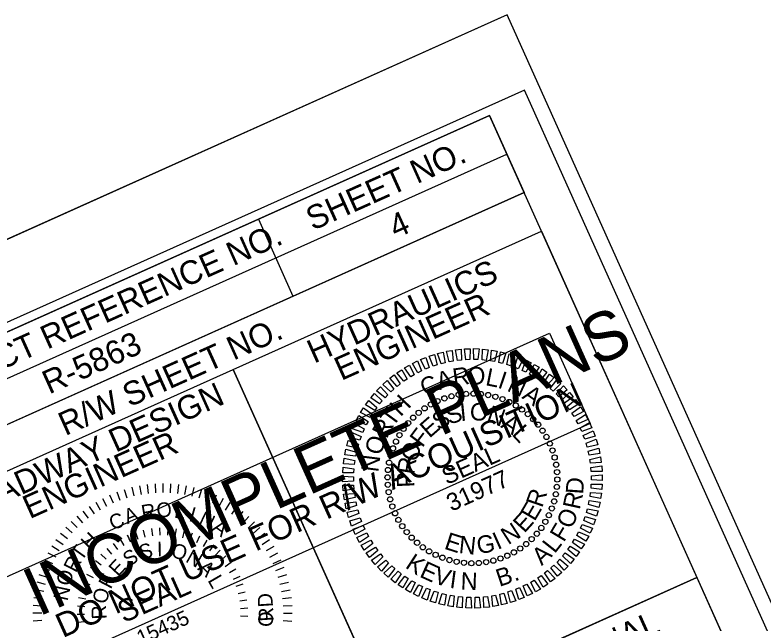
# Model space of a CAD drawing. Extents: x 553939 to 555925, y 502653 to 504347.
# Drawn here: x 555329.1 to 555550.6, y 504166.5 to 504346.6 of the extents above; entities that cross this region are included whole.
import ezdxf

# ---------------------------------------------------------------- set-up
doc = ezdxf.new("R2010")
doc.units = 0
for name, color, linetype in [('Default', 7, 'Continuous'), ('Old_Level_21', 7, 'Continuous'), ('Sheet Border Standard 30in CELL', 7, 'Continuous'), ('Sheet Cutting Line CELL', 7, 'Continuous'), ('Sheet Data Field CELL', 7, 'Continuous'), ('Sheet Plot Border Inside CELL', 7, 'Continuous'), ('Sheet Plot Border Outside CELL', 7, 'Continuous'), ('Sheet Sticker Exception Certification CELL', 7, 'Continuous'), ('Sheet Sticker Incomplete CELL', 7, 'Continuous')]:
    doc.layers.add(name, color=color, linetype=linetype)

msp = doc.modelspace()

# ---------------------------------------------------------------- linework, layer by layer
at = {"layer": 'Default'}
for points in [[(555455.32, 504243.3), (555454.29, 504246.36), (555455.92, 504246.75), (555456.47, 504243.6)], [(555457.72, 504243.86), (555456.9, 504246.99), (555458.55, 504247.26), (555458.88, 504244.08)], [(555460.14, 504244.26), (555459.55, 504247.43), (555461.21, 504247.59), (555461.32, 504244.39)], [(555462.59, 504244.48), (555462.22, 504247.69), (555463.89, 504247.73), (555463.77, 504244.53)], [(555465.05, 504244.53), (555464.9, 504247.76), (555466.57, 504247.68), (555466.23, 504244.51)], [(555467.5, 504244.41), (555467.58, 504247.65), (555469.24, 504247.45), (555468.68, 504244.3)], [(555469.94, 504244.13), (555470.25, 504247.34), (555471.89, 504247.03), (555471.11, 504243.93)], [(555472.36, 504243.67), (555472.89, 504246.86), (555474.51, 504246.43), (555473.51, 504243.39)], [(555450.68, 504241.68), (555449.24, 504244.57), (555450.8, 504245.18), (555451.78, 504242.13)], [(555452.98, 504242.57), (555451.73, 504245.55), (555453.33, 504246.05), (555454.1, 504242.95)], [(555474.74, 504243.04), (555475.48, 504246.19), (555477.07, 504245.65), (555475.87, 504242.69)], [(555477.06, 504242.25), (555478.03, 504245.34), (555479.57, 504244.69), (555478.17, 504241.82)], [(555479.33, 504241.3), (555480.51, 504244.31), (555482, 504243.56), (555480.4, 504240.79)], [(555446.32, 504239.43), (555444.48, 504242.09), (555445.94, 504242.91), (555447.33, 504240.03)], [(555448.46, 504240.63), (555446.81, 504243.41), (555448.33, 504244.13), (555449.52, 504241.16)], [(555481.53, 504240.19), (555482.91, 504243.11), (555484.35, 504242.26), (555482.56, 504239.61)], [(555442.3, 504236.59), (555440.11, 504238.97), (555441.45, 504239.99), (555443.23, 504237.33)], [(555444.26, 504238.08), (555442.24, 504240.61), (555443.64, 504241.53), (555445.23, 504238.75)], [(555483.64, 504238.94), (555485.22, 504241.75), (555486.6, 504240.8), (555484.63, 504238.28)], [(555485.66, 504237.53), (555487.44, 504240.23), (555488.74, 504239.19), (555486.6, 504236.82)], [(555440.46, 504234.97), (555438.1, 504237.19), (555439.36, 504238.3), (555441.33, 504235.78)], [(555487.58, 504235.99), (555489.54, 504238.56), (555490.77, 504237.43), (555488.46, 504235.21)], [(555438.72, 504233.23), (555436.22, 504235.28), (555437.4, 504236.47), (555439.54, 504234.09)], [(555489.38, 504234.33), (555491.52, 504236.75), (555492.66, 504235.53), (555490.21, 504233.48)], [(555437.12, 504231.37), (555434.48, 504233.24), (555435.58, 504234.51), (555437.87, 504232.28)], [(555491.06, 504232.54), (555493.37, 504234.81), (555494.42, 504233.51), (555491.84, 504231.64)], [(555435.65, 504229.4), (555432.89, 504231.08), (555433.89, 504232.42), (555436.33, 504230.36)], [(555492.62, 504230.63), (555495.07, 504232.74), (555496.04, 504231.37), (555493.33, 504229.68)], [(555434.32, 504227.33), (555431.45, 504228.82), (555432.35, 504230.22), (555434.93, 504228.34)], [(555494.04, 504228.62), (555496.63, 504230.55), (555497.5, 504229.12), (555494.68, 504227.63)], [(555433.14, 504225.17), (555430.17, 504226.46), (555430.97, 504227.92), (555433.68, 504226.23)], [(555495.31, 504226.52), (555498.04, 504228.27), (555498.8, 504226.78), (555495.88, 504225.48)], [(555432.11, 504222.94), (555429.06, 504224.01), (555429.76, 504225.53), (555432.58, 504224.03)], [(555496.44, 504224.34), (555499.28, 504225.89), (555499.94, 504224.35), (555496.93, 504223.26)], [(555431.23, 504220.64), (555428.12, 504221.5), (555428.71, 504223.07), (555431.63, 504221.76)], [(555497.41, 504222.08), (555500.35, 504223.43), (555500.9, 504221.84), (555497.83, 504220.97)], [(555430.53, 504218.29), (555427.36, 504218.93), (555427.84, 504220.53), (555430.84, 504219.43)], [(555498.22, 504219.76), (555501.24, 504220.9), (555501.68, 504219.28), (555498.56, 504218.62)], [(555429.98, 504215.89), (555426.78, 504216.31), (555427.15, 504217.94), (555430.22, 504217.05)], [(555498.86, 504217.39), (555501.96, 504218.31), (555502.29, 504216.67), (555499.12, 504216.23)], [(555499.34, 504214.97), (555502.5, 504215.68), (555502.71, 504214.02), (555499.52, 504213.8)], [(555429.61, 504213.46), (555426.38, 504213.65), (555426.64, 504215.31), (555429.76, 504214.64)], [(555429.4, 504211.01), (555426.17, 504210.98), (555426.31, 504212.65), (555429.47, 504212.19)], [(555499.65, 504212.54), (555502.85, 504213.02), (555502.95, 504211.35), (555499.75, 504211.36)], [(555429.37, 504208.55), (555426.15, 504208.29), (555426.17, 504209.97), (555429.36, 504209.74)], [(555499.79, 504210.08), (555503.02, 504210.34), (555502.99, 504208.67), (555499.81, 504208.9)], [(555429.51, 504206.1), (555426.31, 504205.61), (555426.22, 504207.29), (555429.42, 504207.28)], [(555499.76, 504207.62), (555502.99, 504207.66), (555502.85, 504205.99), (555499.69, 504206.44)], [(555429.82, 504203.66), (555426.67, 504202.95), (555426.45, 504204.62), (555429.64, 504204.83)], [(555499.56, 504205.17), (555502.78, 504204.98), (555502.53, 504203.33), (555499.4, 504204)], [(555430.3, 504201.25), (555427.2, 504200.32), (555426.88, 504201.97), (555430.04, 504202.41)], [(555499.18, 504202.74), (555502.39, 504202.33), (555502.02, 504200.7), (555498.95, 504201.58)], [(555430.95, 504198.88), (555427.92, 504197.74), (555427.48, 504199.35), (555430.61, 504200.01)], [(555498.64, 504200.35), (555501.81, 504199.71), (555501.33, 504198.11), (555498.33, 504199.21)], [(555497.93, 504197.99), (555501.05, 504197.14), (555500.45, 504195.57), (555497.54, 504196.88)], [(555431.76, 504196.56), (555428.82, 504195.21), (555428.27, 504196.79), (555431.34, 504197.67)], [(555497.06, 504195.69), (555500.11, 504194.62), (555499.41, 504193.1), (555496.59, 504194.61)], [(555432.73, 504194.3), (555429.89, 504192.75), (555429.23, 504194.29), (555432.23, 504195.37)], [(555496.03, 504193.46), (555499, 504192.18), (555498.19, 504190.71), (555495.49, 504192.41)], [(555433.85, 504192.11), (555431.13, 504190.37), (555430.36, 504191.86), (555433.28, 504193.15)], [(555494.85, 504191.31), (555497.72, 504189.82), (555496.81, 504188.41), (555494.23, 504190.3)], [(555435.13, 504190.01), (555432.53, 504188.08), (555431.66, 504189.51), (555434.49, 504191.01)], [(555436.55, 504188), (555434.09, 504185.9), (555433.13, 504187.27), (555435.84, 504188.95)], [(555493.52, 504189.24), (555496.28, 504187.56), (555495.28, 504186.21), (555492.83, 504188.27)], [(555438.1, 504186.1), (555435.8, 504183.83), (555434.74, 504185.13), (555437.33, 504187)], [(555492.05, 504187.27), (555494.68, 504185.4), (555493.59, 504184.13), (555491.3, 504186.35)], [(555439.78, 504184.31), (555437.65, 504181.88), (555436.5, 504183.1), (555438.95, 504185.15)], [(555490.44, 504185.41), (555492.94, 504183.36), (555491.76, 504182.17), (555489.63, 504184.55)], [(555441.59, 504182.64), (555439.63, 504180.07), (555438.4, 504181.21), (555440.7, 504183.42)], [(555488.71, 504183.66), (555491.06, 504181.44), (555489.8, 504180.34), (555487.84, 504182.86)], [(555443.51, 504181.1), (555441.73, 504178.4), (555440.42, 504179.45), (555442.57, 504181.82)], [(555445.53, 504179.7), (555443.94, 504176.88), (555442.56, 504177.84), (555444.54, 504180.35)], [(555484.9, 504180.55), (555486.92, 504178.03), (555485.52, 504177.11), (555483.93, 504179.88)], [(555486.86, 504182.04), (555489.05, 504179.66), (555487.72, 504178.65), (555485.94, 504181.3)], [(555447.64, 504178.44), (555446.25, 504175.52), (555444.81, 504176.38), (555446.61, 504179.02)], [(555480.7, 504178.01), (555482.35, 504175.22), (555480.84, 504174.51), (555479.65, 504177.47)], [(555482.85, 504179.21), (555484.69, 504176.55), (555483.23, 504175.73), (555481.83, 504178.6)], [(555449.83, 504177.34), (555448.66, 504174.33), (555447.16, 504175.08), (555448.76, 504177.84)], [(555452.1, 504176.39), (555451.14, 504173.3), (555449.59, 504173.95), (555451, 504176.82)], [(555454.43, 504175.6), (555453.68, 504172.45), (555452.09, 504172.99), (555453.3, 504175.95)], [(555476.19, 504176.07), (555477.43, 504173.08), (555475.83, 504172.59), (555475.07, 504175.69)], [(555478.48, 504176.96), (555479.93, 504174.07), (555478.37, 504173.46), (555477.39, 504176.5)], [(555456.81, 504174.97), (555456.28, 504171.78), (555454.66, 504172.2), (555455.65, 504175.24)], [(555459.22, 504174.51), (555458.92, 504171.29), (555457.27, 504171.6), (555458.05, 504174.7)], [(555461.66, 504174.22), (555461.58, 504170.99), (555459.92, 504171.18), (555460.48, 504174.33)], [(555464.12, 504174.1), (555464.27, 504170.87), (555462.59, 504170.95), (555462.93, 504174.13)], [(555466.57, 504174.16), (555466.95, 504170.94), (555465.27, 504170.91), (555465.39, 504174.1)], [(555469.02, 504174.38), (555469.62, 504171.2), (555467.95, 504171.05), (555467.85, 504174.24)], [(555471.45, 504174.78), (555472.27, 504171.65), (555470.61, 504171.38), (555470.29, 504174.56)], [(555473.84, 504175.34), (555474.87, 504172.27), (555473.24, 504171.89), (555472.7, 504175.04)]]:
    msp.add_lwpolyline(points, close=True, dxfattribs=at)
for centre in [(555456.29, 504233.03), (555458.38, 504233.67), (555460.53, 504234.11), (555462.71, 504234.37), (555464.9, 504234.44), (555467.09, 504234.32), (555469.26, 504234.01), (555471.39, 504233.5), (555473.47, 504232.82), (555452.29, 504231.23), (555454.25, 504232.22), (555475.49, 504231.95), (555477.42, 504230.92), (555448.67, 504228.77), (555450.43, 504230.08), (555479.25, 504229.72), (555480.97, 504228.36), (555447.04, 504227.31), (555482.57, 504226.86), (555444.18, 504223.99), (555445.54, 504225.71), (555484.03, 504225.23), (555442.98, 504222.15), (555485.34, 504223.47), (555486.5, 504221.61), (555441.95, 504220.22), (555487.49, 504219.65), (555441.08, 504218.21), (555488.3, 504217.61), (555440.4, 504216.12), (555488.93, 504215.52), (555439.9, 504213.99), (555489.38, 504213.37), (555439.58, 504211.82), (555489.64, 504211.19), (555439.46, 504209.63), (555489.71, 504209), (555439.53, 504207.44), (555489.58, 504206.81), (555439.79, 504205.27), (555489.27, 504204.64), (555440.23, 504203.12), (555488.77, 504202.51), (555440.87, 504201.02), (555488.08, 504200.43), (555441.68, 504198.99), (555442.67, 504197.03), (555487.22, 504198.41), (555443.82, 504195.17), (555486.18, 504196.48), (555445.13, 504193.41), (555483.63, 504192.93), (555484.98, 504194.65), (555446.59, 504191.78), (555482.12, 504191.33), (555448.19, 504190.27), (555449.91, 504188.92), (555478.73, 504188.56), (555480.49, 504189.87), (555451.75, 504187.72), (555453.68, 504186.68), (555474.91, 504186.41), (555476.87, 504187.4), (555455.69, 504185.82), (555457.78, 504185.13), (555459.91, 504184.63), (555462.08, 504184.32), (555464.27, 504184.19), (555466.46, 504184.26), (555468.63, 504184.52), (555470.78, 504184.97), (555472.88, 504185.6)]:
    msp.add_circle(centre, 0.777, dxfattribs=at)
at = {"layer": 'Old_Level_21'}
for p, q in [((555363.74, 504206.68), (555364.36, 504204.14)), ((555366, 504207.16), (555366.47, 504204.58)), ((555368.3, 504207.5), (555368.61, 504204.9)), ((555370.61, 504207.71), (555370.76, 504205.09)), ((555372.93, 504207.77), (555372.92, 504205.15)), ((555375.24, 504207.7), (555375.08, 504205.08)), ((555377.56, 504207.48), (555377.23, 504204.88)), ((555379.85, 504207.13), (555379.37, 504204.56)), ((555359.31, 504205.31), (555360.23, 504202.86)), ((555361.5, 504206.06), (555362.28, 504203.56)), ((555382.11, 504206.63), (555381.48, 504204.1)), ((555384.35, 504206.01), (555383.56, 504203.51)), ((555386.54, 504205.24), (555385.6, 504202.8)), ((555353.05, 504202.28), (555354.4, 504200.04)), ((555355.07, 504203.41), (555356.28, 504201.09)), ((555357.16, 504204.42), (555358.23, 504202.04)), ((555388.67, 504204.35), (555387.6, 504201.97)), ((555390.76, 504203.33), (555389.54, 504201.02)), ((555351.1, 504201.03), (555352.58, 504198.87)), ((555392.78, 504202.19), (555391.42, 504199.95)), ((555394.72, 504200.93), (555393.23, 504198.77)), ((555347.44, 504198.17), (555349.18, 504196.21)), ((555349.23, 504199.66), (555350.84, 504197.59)), ((555396.59, 504199.55), (555394.97, 504197.49)), ((555398.36, 504198.06), (555396.62, 504196.1)), ((555345.75, 504196.59), (555347.6, 504194.73)), ((555400.05, 504196.47), (555398.2, 504194.62)), ((555344.16, 504194.9), (555346.11, 504193.16)), ((555364.79, 504193.37), (555365.48, 504191.3)), ((555367.14, 504194.03), (555367.63, 504191.91)), ((555369.54, 504194.47), (555369.83, 504192.3)), ((555371.98, 504194.67), (555372.06, 504192.49)), ((555374.43, 504194.63), (555374.29, 504192.46)), ((555376.86, 504194.36), (555376.51, 504192.21)), ((555379.25, 504193.86), (555378.7, 504191.75)), ((555401.64, 504194.78), (555399.67, 504193.04)), ((555341.29, 504191.26), (555343.44, 504189.77)), ((555342.67, 504193.13), (555344.73, 504191.51)), ((555360.33, 504191.37), (555361.4, 504189.48)), ((555362.51, 504192.48), (555363.4, 504190.49)), ((555363.4, 504190.49), (555362.51, 504192.48)), ((555381.58, 504193.12), (555380.83, 504191.08)), ((555383.83, 504192.17), (555382.88, 504190.21)), ((555403.12, 504192.99), (555401.05, 504191.38)), ((555340.03, 504189.31), (555342.27, 504187.96)), ((555358.26, 504190.06), (555359.52, 504188.28)), ((555385.98, 504191.01), (555384.85, 504189.14)), ((555388, 504189.64), (555386.7, 504187.89)), ((555404.49, 504191.12), (555402.33, 504189.64)), ((555405.74, 504189.17), (555403.5, 504187.82)), ((555338.89, 504187.3), (555341.2, 504186.08)), ((555354.56, 504186.88), (555356.14, 504185.37)), ((555356.34, 504188.56), (555357.76, 504186.9)), ((555389.89, 504188.08), (555388.42, 504186.47)), ((555406.87, 504187.15), (555404.55, 504185.94)), ((555337.87, 504185.21), (555340.25, 504184.14)), ((555352.96, 504185.03), (555354.67, 504183.68)), ((555391.61, 504186.34), (555389.99, 504184.88)), ((555407.89, 504185.06), (555405.5, 504183.99)), ((555336.98, 504183.07), (555339.42, 504182.14)), ((555351.54, 504183.04), (555353.38, 504181.86)), ((555393.16, 504184.45), (555391.41, 504183.15)), ((555394.52, 504182.42), (555392.66, 504181.3)), ((555408.77, 504182.91), (555406.32, 504181.99)), ((555336.21, 504180.88), (555338.71, 504180.1)), ((555350.32, 504180.92), (555352.26, 504179.92)), ((555395.68, 504180.27), (555393.72, 504179.33)), ((555409.52, 504180.72), (555407.02, 504179.94)), ((555335.59, 504178.65), (555338.12, 504178.02)), ((555349.31, 504178.69), (555351.34, 504177.89)), ((555396.63, 504178.01), (555394.58, 504177.27)), ((555410.14, 504178.48), (555407.6, 504177.86)), ((555335.09, 504176.39), (555337.66, 504175.91)), ((555348.52, 504176.38), (555350.62, 504175.77)), ((555395.22, 504175.21), (555397.33, 504175.76)), ((555410.62, 504176.22), (555408.05, 504175.75)), ((555334.74, 504174.09), (555337.34, 504173.77)), ((555347.96, 504174), (555350.11, 504173.6)), ((555410.97, 504173.92), (555408.36, 504173.61)), ((555334.52, 504171.78), (555337.14, 504171.62)), ((555347.63, 504171.58), (555349.81, 504171.38)), ((555397.84, 504173.28), (555395.69, 504172.94)), ((555411.17, 504171.61), (555408.55, 504171.46)), ((555334.45, 504169.46), (555337.07, 504169.46)), ((555347.54, 504169.13), (555349.72, 504169.15)), ((555398.1, 504170.85), (555395.93, 504170.72)), ((555411.23, 504169.29), (555408.62, 504169.3)), ((555334.51, 504167.15), (555337.13, 504167.3)), ((555347.68, 504166.69), (555349.85, 504166.92)), ((555398.12, 504168.41), (555395.95, 504168.49)), ((555411.16, 504166.98), (555408.55, 504167.14))]:
    msp.add_line(p, q, dxfattribs=at)
at = {"layer": 'Sheet Border Standard 30in CELL'}
for p, q in [((555292.25, 504223.45), (555474.75, 504305.4)), ((555297.37, 504212.05), (555479.87, 504294)), ((555297.37, 504212.05), (555479.87, 504294)), ((555401.21, 504286.08), (555411.45, 504263.27)), ((555393.76, 504241.63), (555439.82, 504139.05))]:
    msp.add_line(p, q, dxfattribs=at)
for points in [[(555469.6, 504316.85), (554101.23, 503702.4), (554531.34, 502744.54), (555899.72, 503358.98)], [(555287.11, 504234.9), (555469.6, 504316.85), (555479.87, 504294), (555297.37, 504212.05)], [(555393.76, 504241.63), (555484.99, 504282.59), (555531.07, 504179.96), (555439.84, 504139)], [(555302.49, 504200.65), (555393.76, 504241.63), (555439.84, 504139), (555348.57, 504098.02)]]:
    msp.add_lwpolyline(points, close=True, dxfattribs=at)
at = {"layer": 'Sheet Cutting Line CELL'}
msp.add_line((555474.87, 504346.62), (553938.64, 503656.8), dxfattribs=at)
at = {"layer": 'Sheet Plot Border Inside CELL'}
msp.add_lwpolyline([(555479.96, 504324.29), (553959.7, 503641.65), (554391.9, 502679.13), (555912.16, 503361.78)], close=True, dxfattribs=at)
at = {"layer": 'Sheet Plot Border Outside CELL'}
msp.add_lwpolyline([(555474.87, 504346.62), (553938.64, 503656.8), (554389.23, 502653.32), (555925.47, 503343.14)], close=True, dxfattribs=at)
at = {"layer": 'Sheet Sticker Exception Certification CELL'}
for p, q in [((555348.57, 504098.02), (555531.06, 504179.96)), ((555531.06, 504179.95), (555540.69, 504158.51))]:
    msp.add_line(p, q, dxfattribs=at)
at = {"layer": 'Sheet Sticker Incomplete CELL'}
msp.add_lwpolyline([(555331.81, 504150.28), (555319.77, 504177.08), (555487.4, 504252.35), (555499.43, 504225.55)], close=True, dxfattribs=at)

# ---------------------------------------------------------------- texts
at = {"layer": 'Default'}
for s, height, rotation, p in [('R', 5.18, 7.6906, (555459.06, 504236.67)), ('O', 5.18, 359.4819, (555463.02, 504237.18)), ('A', 5.18, 16.7381, (555454.83, 504235.46)), ('L', 5.18, 348.7567, (555468.23, 504236.98)), ('I', 5.18, 341.2916, (555471.8, 504236.27)), ('C', 5.18, 26.2431, (555450.64, 504233.49)), ('N', 5.18, 335.3516, (555474.55, 504235.38)), ('A', 5.18, 325.1412, (555479.01, 504233.2)), ('H', 5.18, 45.8823, (555443.33, 504227.4)), ('S', 5.18, 17.546, (555457.66, 504225.2)), ('I', 5.18, 5.5871, (555461.1, 504226.28)), ('O', 5.18, 356.8316, (555463.72, 504226.62)), ('T', 5.18, 53.6715, (555441.07, 504224.35)), ('S', 5.18, 29.505, (555454.52, 504223.42)), ('N', 5.18, 341.0229, (555468.47, 504226.2)), ('R', 5.18, 61.8802, (555439.17, 504220.84)), ('E', 5.18, 41.2672, (555451.86, 504221.07)), ('A', 5.18, 325.9728, (555472.72, 504224.61)), ('F', 5.18, 52.9452, (555449.74, 504218.25)), ('L', 5.18, 312.6369, (555476.03, 504222.32)), ('O', 5.18, 72.6054, (555437.47, 504215.91)), ('O', 5.18, 68.7539, (555447.87, 504213.87)), ('SEAL', 5.181, 24.2813, (555456.99, 504207.31)), ('N', 5.18, 82.8158, (555436.73, 504211)), ('R', 5.18, 80.8534, (555447.29, 504210.27)), ('31977', 5.181, 24.2813, (555458.37, 504199.41)), ('P', 5.18, 92.6156, (555447.46, 504206.72)), ('D', 5.18, 85.9818, (555497.35, 504204.5)), ('R', 5.18, 71.3242, (555485.23, 504200.43)), ('R', 5.18, 77.7731, (555496.33, 504199.87)), ('E', 5.18, 59.562, (555482.98, 504196.4)), ('O', 5.18, 67.0479, (555494.02, 504194.13)), ('E', 5.18, 47.7997, (555479.96, 504192.92)), ('N', 5.18, 32.7497, (555475.18, 504189.49)), ('F', 5.18, 59.1253, (555491.64, 504190.22)), ('I', 5.18, 23.9942, (555472.04, 504188.11)), ('E', 5.18, 342.1319, (555455.98, 504188.55)), ('N', 5.18, 353.8941, (555460.4, 504187.23)), ('G', 5.18, 8.9442, (555466.27, 504186.9)), ('A', 5.18, 42.6126, (555485.1, 504183.31)), ('L', 5.18, 51.6601, (555488.93, 504186.86)), ('K', 5.18, 326.895, (555444.44, 504183.02)), ('E', 5.18, 335.5994, (555448.65, 504180.28)), ('V', 5.18, 343.5793, (555452.84, 504178.35)), ('B', 5.18, 18.3012, (555472.57, 504177.17)), ('I', 5.18, 352.2645, (555457.65, 504176.93)), ('N', 5.18, 358.2045, (555461.04, 504176.39)), ('.', 5.18, 26.6433, (555477.15, 504178.67))]:
    msp.add_text(s, height=height, rotation=rotation, dxfattribs=at).set_placement(p)
at = {"layer": 'Old_Level_21'}
for s, height, rotation, p in [('O', 4.36, 6.3926, (555371.29, 504197.62)), ('A', 4.36, 21.4587, (555362.44, 504195.75)), ('R', 4.36, 9.4494, (555366.92, 504197.04)), ('L', 4.36, 353.2563, (555376.13, 504197.66)), ('I', 4.36, 343.6808, (555380.37, 504196.79)), ('C', 4.36, 21.4587, (555358.06, 504193.88)), ('N', 4.36, 334.3864, (555383.2, 504195.8)), ('A', 4.36, 324.6188, (555387.14, 504194.04)), ('H', 4.36, 45.1694, (555351.29, 504187.78)), ('T', 4.36, 54.6013, (555348.86, 504184.62)), ('S', 4.36, 16.4536, (555366.62, 504185.15)), ('I', 4.36, 1.1574, (555371.23, 504186.18)), ('O', 4.36, 345.8611, (555375.13, 504186.06)), ('S', 4.36, 31.7499, (555362.79, 504183.04)), ('N', 4.36, 330.5649, (555379.39, 504184.77)), ('R', 4.36, 62.7623, (555347.18, 504181.19)), ('E', 4.36, 47.0461, (555359.67, 504180)), ('A', 4.36, 315.2686, (555383.03, 504182.49)), ('O', 4.36, 75.819, (555345.5, 504177.23)), ('F', 4.36, 62.3424, (555357.49, 504176.32)), ('SEAL', 6.542, 24.1017, (555361.34, 504166.38)), ('L', 4.36, 299.9724, (555386.08, 504179.13)), ('N', 4.36, 77.7785, (555344.72, 504172.84)), ('O', 4.36, 77.6386, (555356.28, 504171.93)), (' RD', 4.358, 93.7742, (555405.93, 504165.46)), ('R', 4.36, 92.9348, (555356.3, 504167.66)), ('15435', 4.358, 24.1017, (555366.4, 504159.86)), ('O ', 4.358, 85.1014, (555405.36, 504165.18))]:
    msp.add_text(s, height=height, rotation=rotation, dxfattribs=at).set_placement(p)
at = {"layer": 'Sheet Border Standard 30in CELL'}
for s, p in [('SHEET NO.', (555417.33, 504282.63)), ('PROJECT REFERENCE NO.', (555296.5, 504228.49)), ('HYDRAULICS', (555417.7, 504243.28)), ('ENGINEER', (555425.76, 504238.18)), ('R/W SHEET NO.', (555344.05, 504221.83)), ('ROADWAY DESIGN', (555312.45, 504196.02)), ('ENGINEER', (555333.5, 504197.2))]:
    msp.add_text(s, height=7, rotation=24.1816, dxfattribs=at).set_placement(p)
at = {"layer": 'Sheet Data Field CELL'}
for s, p in [('4', (555441.9, 504280.29)), ('R-5863', (555339.27, 504234.15))]:
    msp.add_text(s, height=7, rotation=24.1816, dxfattribs=at).set_placement(p)
at = {"layer": 'Sheet Sticker Exception Certification CELL'}
msp.add_text('DOCUMENT NOT CONSIDERED FINAL', height=7, rotation=24.1816, dxfattribs=at).set_placement((555365.03, 504094.07))
at = {"layer": 'Sheet Sticker Incomplete CELL'}
for s, height, p in [('INCOMPLETE PLANS', 14.4, (555336.03, 504168.23)), ('DO NOT USE FOR R/W ACQUISITION', 7.2, (555343.29, 504161.97))]:
    msp.add_text(s, height=height, rotation=24.1816, dxfattribs=at).set_placement(p)

doc.saveas('drawing.dxf')
